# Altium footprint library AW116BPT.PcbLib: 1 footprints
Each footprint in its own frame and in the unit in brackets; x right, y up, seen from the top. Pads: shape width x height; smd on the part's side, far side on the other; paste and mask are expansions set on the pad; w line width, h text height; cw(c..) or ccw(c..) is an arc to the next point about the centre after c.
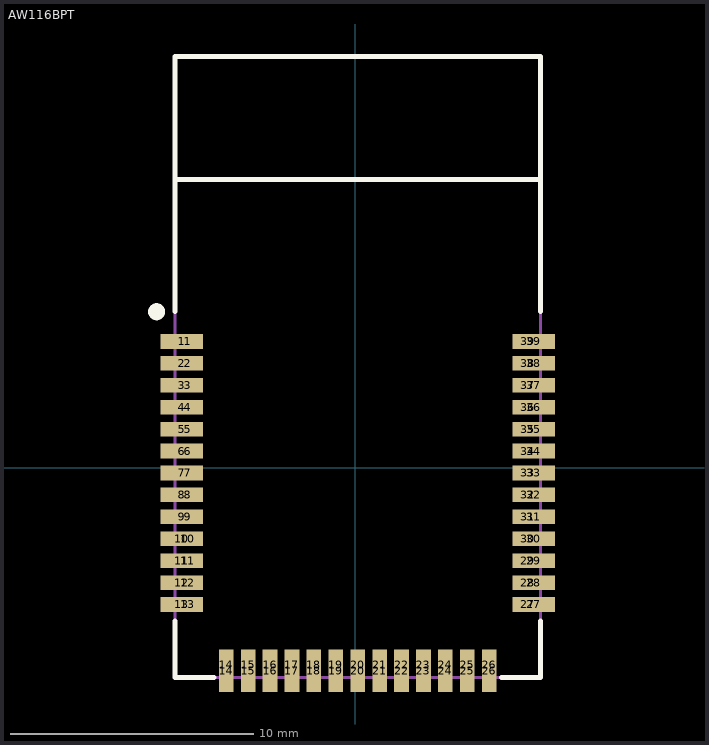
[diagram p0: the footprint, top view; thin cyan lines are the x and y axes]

## AW116BPT [mm]
pads (78):
  rect 1.75x0.6 smd mask+0.038: 1(-7.133,5.191) 2(-7.133,4.291) 3(-7.133,3.391) 4(-7.133,2.491) 5(-7.133,1.591) 6(-7.133,0.691) 7(-7.133,-0.209) 8(-7.133,-1.109) 9(-7.133,-2.009) 10(-7.133,-2.909) 11(-7.133,-3.809) 12(-7.133,-4.709) 13(-7.133,-5.609) 27(7.317,-5.609) 28(7.317,-4.709) 29(7.317,-3.809) 30(7.317,-2.909) 31(7.317,-2.009) 32(7.317,-1.109) 33(7.317,-0.209) 34(7.317,0.691) 35(7.317,1.591) 36(7.317,2.491) 37(7.317,3.391) 38(7.317,4.291) 39(7.317,5.191)
  rect 1.05x0.6 on Mech15 mask+0.051: 1(-6.883,5.191) 2(-6.883,4.291) 3(-6.883,3.391) 4(-6.883,2.491) 5(-6.883,1.591) 6(-6.883,0.691) 7(-6.883,-0.209) 8(-6.883,-1.109) 9(-6.883,-2.009) 10(-6.883,-2.909) 11(-6.883,-3.809) 12(-6.883,-4.709) 13(-6.883,-5.609) 27(7.067,-5.609) 28(7.067,-4.709) 29(7.067,-3.809) 30(7.067,-2.909) 31(7.067,-2.009) 32(7.067,-1.109) 33(7.067,-0.209) 34(7.067,0.691) 35(7.067,1.591) 36(7.067,2.491) 37(7.067,3.391) 38(7.067,4.291) 39(7.067,5.191)
  rect 0.6x1.05 on Mech15 mask+0.051: 14(-5.308,-8.084) 15(-4.408,-8.084) 16(-3.508,-8.084) 17(-2.608,-8.084) 18(-1.708,-8.084) 19(-0.808,-8.084) 20(0.092,-8.084) 21(0.992,-8.084) 22(1.892,-8.084) 23(2.792,-8.084) 24(3.692,-8.084) 25(4.592,-8.084) 26(5.492,-8.084)
  rect 0.6x1.75 smd mask+0.038: 14(-5.308,-8.334) 15(-4.408,-8.334) 16(-3.508,-8.334) 17(-2.608,-8.334) 18(-1.708,-8.334) 19(-0.808,-8.334) 20(0.092,-8.334) 21(0.992,-8.334) 22(1.892,-8.334) 23(2.792,-8.334) 24(3.692,-8.334) 25(4.592,-8.334) 26(5.492,-8.334)
Top Overlay:
  circle w0.4: c-8.163,6.411 r0.15
  lines w0.2: -7.408,-6.289 -7.408,-8.609 -5.808,-8.609 ; -7.408,6.411 -7.408,16.891 7.592,16.891 7.592,6.411 ; -7.408,11.838 3.742,11.838 7.592,11.838 ; 5.992,-8.609 7.592,-8.609 7.592,-6.289
Mechanical 15:
  lines w0.127: -7.408,11.838 7.578,11.838 ; -7.408,-8.609 7.592,-8.609 7.592,16.891 -7.408,16.891 -7.408,-8.609
Multi-Layer:
  pour cut-out: -7.408,16.918 -7.408,11.584 7.592,11.584 7.592,16.918
3D body: height 0.8, standoff 0, extent -7.394,11.874 7.592,16.891
3D body: height 2.4, standoff 0, extent -7.401,-8.636 7.585,11.871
